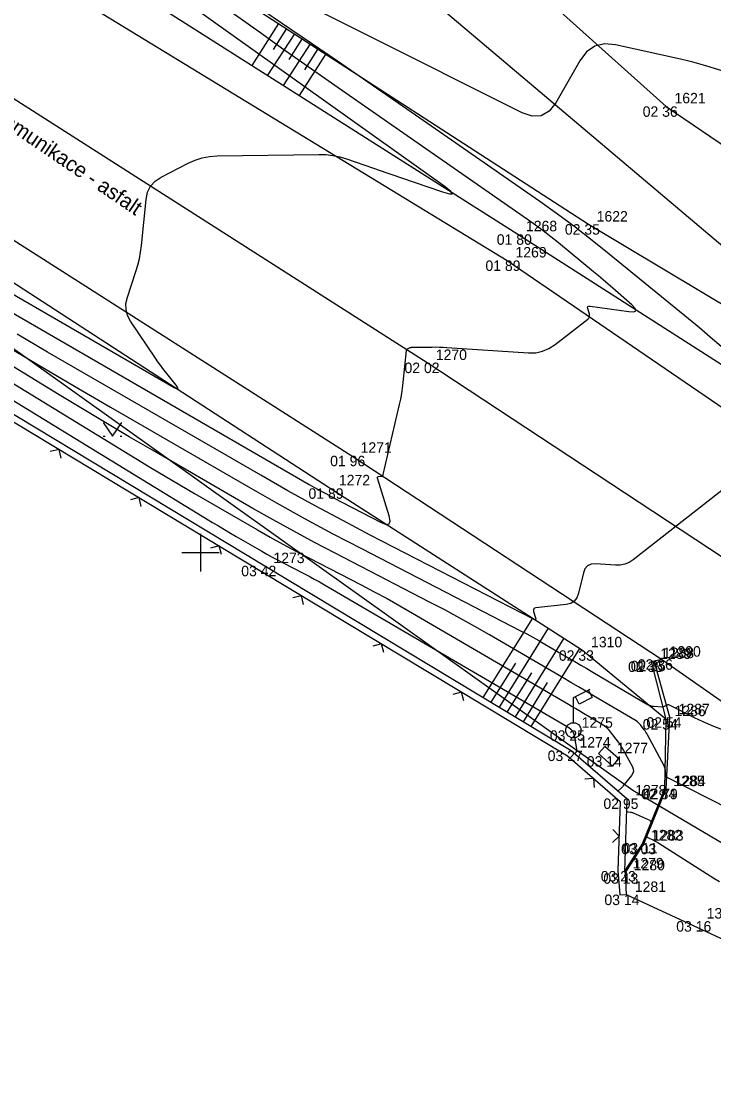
# Model space of a CAD drawing. Extents: x -711234 to -710007, y -1026313 to -1025448.
# Drawn here: x -710604.8 to -710586.27, y -1025538.91 to -1025510.79 of the extents above; entities that cross this region are included whole.
import ezdxf

# ---------------------------------------------------------------- set-up
doc = ezdxf.new("R2010")
doc.units = 0
for name, color, linetype in [('Ex_Major Contours', 7, 'Continuous'), ('Ex_Minor Contours', 7, 'Continuous'), ('Z_body', 7, 'Continuous'), ('Z_body_cisla', 7, 'Continuous'), ('Z_body_vysky_redukovane', 7, 'Continuous'), ('Z_hektometricka_sit', 7, 'Continuous'), ('Z_hrany_paty', 7, 'Continuous'), ('Z_katastr_hranice', 7, 'Continuous'), ('Z_komunikace', 7, 'Continuous'), ('Z_komunikace_osa', 7, 'Continuous'), ('Z_obruba', 7, 'Continuous'), ('Z_pilire', 7, 'Continuous'), ('Z_ploty', 7, 'Continuous'), ('Z_ploty_znacky', 7, 'Continuous'), ('Z_pole_rozhranni', 7, 'Continuous'), ('Z_popisy', 7, 'Continuous'), ('Z_rozhranni', 7, 'Continuous'), ('Z_site_vo_znaky', 7, 'Continuous'), ('Z_technicke_srafy', 7, 'Continuous'), ('Z_vstupy', 7, 'Continuous'), ('Z_znaky_kultur', 7, 'Continuous')]:
    doc.layers.add(name, color=color, linetype=linetype)

# ---------------------------------------------------------------- blocks, each defined once
blk = doc.blocks.new('POINT_DISPLAY')
blk.add_line((0, 0), (0, 0))
blk = doc.blocks.new('Z13')
for p, q in [((0, 0.88), (0.45, 1.1)), ((0, 0.2), (0, 0.88)), ((0.15, 0.7), (0.05, 0.9)), ((0.5, 0.88), (0.15, 0.7)), ((0.4, 1.07), (0.5, 0.88)), ((-0.2, 0.05), (-0.15, 0.15)), ((-0.2, -0.05), (-0.2, 0.05)), ((-0.15, 0.15), (-0.05, 0.2)), ((-0.05, 0.2), (0.05, 0.2)), ((0.05, 0.2), (0.15, 0.15)), ((0.15, 0.15), (0.2, 0.05)), ((0.2, 0.05), (0.2, -0.05)), ((-0.15, -0.15), (-0.2, -0.05)), ((-0.05, -0.2), (-0.15, -0.15)), ((0.05, -0.2), (-0.05, -0.2)), ((0.15, -0.15), (0.05, -0.2)), ((0.2, -0.05), (0.15, -0.15))]:
    blk.add_line(p, q)
blk = doc.blocks.new('Z666')
for p, q in [((-0.25, 0.13), (-0.25, -0.13)), ((0.25, 0.13), (-0.25, 0.13)), ((0.25, -0.13), (0.25, 0.13)), ((-0.25, -0.13), (0.25, -0.13))]:
    blk.add_line(p, q)
blk = doc.blocks.new('Z212')
for p, q in [((-0.17, 0.17), (0, 0)), ((0, 0), (0.17, 0.17))]:
    blk.add_line(p, q)
blk = doc.blocks.new('Z314')
for p, q in [((-0.25, 0.17), (0, -0.2)), ((0, -0.2), (0.25, 0.17)), ((-0.25, -0.2), (-0.2, -0.2)), ((0.2, -0.2), (0.25, -0.2))]:
    blk.add_line(p, q)

msp = doc.modelspace()

# ---------------------------------------------------------------- linework, layer by layer
at = {"layer": 'Ex_Major Contours'}
for points in [[(-710606.138, -1025517.948), (-710597.097, -1025523.174), (-710596.876, -1025523.3), (-710596.653, -1025523.423), (-710596.429, -1025523.544), (-710596.203, -1025523.662), (-710595.169, -1025524.195), (-710595.034, -1025524.247), (-710594.953, -1025524.234), (-710594.927, -1025524.157), (-710594.955, -1025524.015), (-710595.272, -1025523.011), (-710595.275, -1025522.994), (-710595.271, -1025522.981), (-710595.261, -1025522.972), (-710595.244, -1025522.968), (-710595.163, -1025522.959), (-710595.145, -1025522.954), (-710595.131, -1025522.945), (-710595.12, -1025522.932), (-710595.114, -1025522.915), (-710594.677, -1025521.04), (-710594.646, -1025520.894), (-710594.62, -1025520.748), (-710594.598, -1025520.602), (-710594.581, -1025520.454), (-710594.497, -1025519.597), (-710594.494, -1025519.583), (-710594.488, -1025519.571), (-710594.479, -1025519.561), (-710594.467, -1025519.553), (-710594.413, -1025519.525), (-710594.399, -1025519.519), (-710594.385, -1025519.515), (-710594.371, -1025519.512), (-710594.356, -1025519.511), (-710593.805, -1025519.503), (-710593.708, -1025519.502), (-710593.611, -1025519.504), (-710593.514, -1025519.507), (-710593.417, -1025519.513), (-710591.232, -1025519.658), (-710591.039, -1025519.655), (-710590.857, -1025519.617), (-710590.685, -1025519.546), (-710590.523, -1025519.44), (-710589.647, -1025518.755), (-710589.621, -1025518.728), (-710589.605, -1025518.699), (-710589.6, -1025518.665), (-710589.605, -1025518.628), (-710589.647, -1025518.474), (-710589.651, -1025518.441), (-710589.642, -1025518.419), (-710589.622, -1025518.408), (-710589.588, -1025518.408), (-710588.549, -1025518.555), (-710588.418, -1025518.562), (-710588.36, -1025518.535), (-710588.377, -1025518.474), (-710588.467, -1025518.379), (-710588.976, -1025517.931), (-710589.104, -1025517.819), (-710589.233, -1025517.709), (-710589.362, -1025517.6), (-710589.493, -1025517.491), (-710590.432, -1025516.72), (-710590.634, -1025516.558), (-710590.839, -1025516.4), (-710591.047, -1025516.246), (-710591.258, -1025516.096), (-710596.233, -1025512.634), (-710596.768, -1025512.261), (-710597.301, -1025511.887), (-710597.833, -1025511.511), (-710598.364, -1025511.133), (-710601.43, -1025508.946)], [(-710612.856, -1025515.672), (-710601.725, -1025522.486), (-710601.337, -1025522.722), (-710600.947, -1025522.956), (-710600.555, -1025523.187), (-710600.162, -1025523.416), (-710598.479, -1025524.389), (-710598.138, -1025524.583), (-710597.795, -1025524.773), (-710597.45, -1025524.96), (-710597.102, -1025525.142), (-710595.706, -1025525.861), (-710595.359, -1025526.043), (-710595.014, -1025526.23), (-710594.671, -1025526.421), (-710594.331, -1025526.617), (-710590.167, -1025529.05), (-710590.066, -1025529.109), (-710589.965, -1025529.169), (-710589.864, -1025529.228), (-710589.763, -1025529.287), (-710589.309, -1025529.555), (-710589.236, -1025529.603), (-710589.168, -1025529.657), (-710589.106, -1025529.718), (-710589.05, -1025529.786), (-710588.837, -1025530.068), (-710588.785, -1025530.139), (-710588.736, -1025530.213), (-710588.69, -1025530.288), (-710588.647, -1025530.365), (-710588.454, -1025530.726), (-710588.431, -1025530.785), (-710588.427, -1025530.843), (-710588.442, -1025530.898), (-710588.475, -1025530.953), (-710588.707, -1025531.245), (-710588.718, -1025531.258), (-710588.73, -1025531.272), (-710588.742, -1025531.285), (-710588.755, -1025531.297), (-710588.833, -1025531.37)], [(-710588.612, -1025531.916), (-710588.505, -1025531.936), (-710588.487, -1025531.939), (-710588.469, -1025531.944), (-710588.452, -1025531.95), (-710588.435, -1025531.956), (-710588.031, -1025532.13), (-710587.993, -1025532.153), (-710587.97, -1025532.183), (-710587.962, -1025532.22), (-710587.97, -1025532.264), (-710588.058, -1025532.536), (-710588.061, -1025532.548), (-710588.065, -1025532.56), (-710588.072, -1025532.584), (-710588.072, -1025532.59), (-710588.071, -1025532.595), (-710588.068, -1025532.599), (-710588.064, -1025532.602), (-710587.876, -1025532.696), (-710587.843, -1025532.713), (-710587.811, -1025532.731), (-710587.779, -1025532.749), (-710587.747, -1025532.769), (-710586.275, -1025533.7), (-710586.123, -1025533.792)]]:
    msp.add_lwpolyline(points, dxfattribs=at)
at = {"layer": 'Ex_Minor Contours'}
for points in [[(-710601.183, -1025508.56), (-710597.029, -1025511.383), (-710596.333, -1025511.857), (-710595.638, -1025512.334), (-710594.944, -1025512.812), (-710594.251, -1025513.293), (-710590.931, -1025515.603), (-710590.456, -1025515.941), (-710589.988, -1025516.288), (-710589.527, -1025516.643), (-710589.072, -1025517.009), (-710586.958, -1025518.743), (-710586.665, -1025518.986), (-710586.373, -1025519.232), (-710586.084, -1025519.48)], [(-710573.223, -1025517.572), (-710574.002, -1025517.243), (-710574.766, -1025516.876), (-710577.79, -1025515.328), (-710578.551, -1025514.953), (-710579.324, -1025514.603), (-710580.106, -1025514.278), (-710580.9, -1025513.977), (-710585.752, -1025512.226), (-710586.121, -1025512.099), (-710586.494, -1025511.985), (-710586.87, -1025511.883), (-710587.25, -1025511.793), (-710588.909, -1025511.428), (-710589.205, -1025511.402), (-710589.463, -1025511.464), (-710589.682, -1025511.614), (-710589.862, -1025511.85), (-710590.505, -1025512.972), (-710590.682, -1025513.199), (-710590.891, -1025513.32), (-710591.132, -1025513.335), (-710591.405, -1025513.243), (-710599.918, -1025508.97)], [(-710608.19, -1025516.259), (-710600.705, -1025520.585), (-710600.628, -1025520.623), (-710600.594, -1025520.626), (-710600.601, -1025520.591), (-710600.65, -1025520.521), (-710600.933, -1025520.167), (-710601.002, -1025520.078), (-710601.07, -1025519.987), (-710601.136, -1025519.895), (-710601.2, -1025519.802), (-710601.868, -1025518.809), (-710601.949, -1025518.657), (-710601.99, -1025518.5), (-710601.992, -1025518.337), (-710601.954, -1025518.17), (-710601.726, -1025517.488), (-710601.673, -1025517.316), (-710601.631, -1025517.143), (-710601.599, -1025516.967), (-710601.576, -1025516.789), (-710601.455, -1025515.557), (-710601.415, -1025515.367), (-710601.334, -1025515.205), (-710601.213, -1025515.07), (-710601.052, -1025514.963), (-710600.326, -1025514.588), (-710600.141, -1025514.506), (-710599.951, -1025514.446), (-710599.755, -1025514.409), (-710599.554, -1025514.395), (-710596.837, -1025514.356), (-710596.648, -1025514.361), (-710596.462, -1025514.383), (-710596.278, -1025514.421), (-710596.097, -1025514.475), (-710595.377, -1025514.723), (-710595.197, -1025514.785), (-710595.017, -1025514.847), (-710594.836, -1025514.909), (-710594.656, -1025514.971), (-710593.531, -1025515.358), (-710593.341, -1025515.413), (-710593.266, -1025515.409), (-710593.306, -1025515.346), (-710593.462, -1025515.223), (-710601.081, -1025509.788)], [(-710585.859, -1025531.86), (-710587.53, -1025531.006), (-710587.532, -1025531.006), (-710587.534, -1025531.005), (-710587.536, -1025531.006), (-710587.538, -1025531.006), (-710587.546, -1025531.01), (-710587.548, -1025531.011), (-710587.549, -1025531.011), (-710587.55, -1025531.01), (-710587.55, -1025531.008), (-710587.571, -1025530.817), (-710587.576, -1025530.785), (-710587.584, -1025530.754), (-710587.595, -1025530.724), (-710587.609, -1025530.694), (-710588.051, -1025529.868), (-710588.071, -1025529.833), (-710588.092, -1025529.798), (-710588.114, -1025529.765), (-710588.138, -1025529.732), (-710588.235, -1025529.603), (-710588.261, -1025529.572), (-710588.289, -1025529.545), (-710588.32, -1025529.52), (-710588.353, -1025529.498), (-710589.496, -1025528.825), (-710589.698, -1025528.706), (-710589.9, -1025528.587), (-710590.102, -1025528.469), (-710590.304, -1025528.35), (-710592.271, -1025527.201), (-710592.668, -1025526.973), (-710593.067, -1025526.75), (-710593.47, -1025526.532), (-710593.875, -1025526.32), (-710596.401, -1025525.017), (-710596.955, -1025524.727), (-710597.506, -1025524.43), (-710598.054, -1025524.127), (-710598.598, -1025523.817), (-710601.282, -1025522.265), (-710601.909, -1025521.9), (-710602.534, -1025521.531), (-710603.156, -1025521.158), (-710603.776, -1025520.782), (-710612.619, -1025515.368)], [(-710613.093, -1025515.976), (-710599.675, -1025524.191), (-710599.517, -1025524.286), (-710599.359, -1025524.381), (-710599.201, -1025524.475), (-710599.042, -1025524.567), (-710598.361, -1025524.961), (-710598.223, -1025525.04), (-710598.084, -1025525.117), (-710597.944, -1025525.192), (-710597.803, -1025525.266), (-710597.238, -1025525.557), (-710597.098, -1025525.631), (-710596.958, -1025525.706), (-710596.819, -1025525.784), (-710596.682, -1025525.863), (-710590.153, -1025529.678), (-710590.098, -1025529.718), (-710590.055, -1025529.767), (-710590.025, -1025529.825), (-710590.007, -1025529.891), (-710589.94, -1025530.293), (-710589.939, -1025530.302), (-710589.941, -1025530.312), (-710589.945, -1025530.32), (-710589.951, -1025530.327), (-710589.997, -1025530.37)], [(-710584.755, -1025522.311), (-710588.435, -1025525.191), (-710588.543, -1025525.262), (-710588.658, -1025525.31), (-710588.78, -1025525.335), (-710588.91, -1025525.337), (-710589.44, -1025525.302), (-710589.56, -1025525.311), (-710589.654, -1025525.354), (-710589.723, -1025525.431), (-710589.766, -1025525.543), (-710589.892, -1025526.087), (-710589.936, -1025526.206), (-710590.007, -1025526.295), (-710590.104, -1025526.355), (-710590.227, -1025526.385), (-710591.034, -1025526.476), (-710591.071, -1025526.485), (-710591.093, -1025526.504), (-710591.101, -1025526.532), (-710591.095, -1025526.57), (-710591.042, -1025526.738), (-710591.035, -1025526.773), (-710591.042, -1025526.792), (-710591.061, -1025526.795), (-710591.094, -1025526.782), (-710595.46, -1025524.531), (-710596.199, -1025524.145), (-710596.932, -1025523.749), (-710597.661, -1025523.346), (-710598.385, -1025522.933), (-710604.085, -1025519.638), (-710604.899, -1025519.164)], [(-710604.976, -1025519.594), (-710604.121, -1025520.106), (-710603.264, -1025520.613), (-710602.403, -1025521.114), (-710598.717, -1025523.245), (-710597.97, -1025523.671), (-710597.218, -1025524.087), (-710596.461, -1025524.495), (-710595.699, -1025524.893), (-710591.443, -1025527.088), (-710591.279, -1025527.174), (-710591.116, -1025527.262), (-710590.955, -1025527.352), (-710590.794, -1025527.445), (-710590.154, -1025527.818), (-710589.994, -1025527.912), (-710589.835, -1025528.006), (-710589.675, -1025528.1), (-710589.515, -1025528.193), (-710588.051, -1025529.056), (-710588.013, -1025529.075), (-710587.974, -1025529.09), (-710587.933, -1025529.1), (-710587.891, -1025529.106), (-710587.654, -1025529.124), (-710587.643, -1025529.124), (-710587.633, -1025529.123), (-710587.622, -1025529.12), (-710587.612, -1025529.116), (-710587.557, -1025529.088), (-710587.551, -1025529.086), (-710587.54, -1025529.083), (-710587.535, -1025529.08), (-710587.51, -1025529.062), (-710587.506, -1025529.06), (-710587.501, -1025529.058), (-710587.496, -1025529.059), (-710587.491, -1025529.061), (-710586.804, -1025529.406), (-710586.687, -1025529.463), (-710586.569, -1025529.517), (-710586.45, -1025529.568), (-710586.329, -1025529.617), (-710584.508, -1025530.326)]]:
    msp.add_lwpolyline(points, dxfattribs=at)
at = {"layer": 'Z_hektometricka_sit'}
for p, q in [((-710600, -1025524.5), (-710600, -1025525.5)), ((-710600.5, -1025525), (-710599.5, -1025525))]:
    msp.add_line(p, q, dxfattribs=at)
at = {"layer": 'Z_hrany_paty'}
for p, q in [((-710601.64, -1025508.44), (-710589.63, -1025516.22)), ((-710601.22, -1025510.33), (-710591.52, -1025516.49)), ((-710611.31, -1025513.69), (-710596.53, -1025523.28)), ((-710589.63, -1025516.22), (-710581.54, -1025521.06)), ((-710591.52, -1025516.49), (-710579.78, -1025523.99)), ((-710596.53, -1025523.28), (-710589.79, -1025527.61)), ((-710589.79, -1025527.61), (-710587.55, -1025529.45))]:
    msp.add_line(p, q, dxfattribs=at)
at = {"layer": 'Z_katastr_hranice'}
for points in [[(-710600.21, -1025504.82), (-710580.45, -1025521.54), (-710492.86, -1025583.88), (-710429.93, -1025627.5), (-710391.58, -1025654.85), (-710379.57, -1025662.83), (-710367.07, -1025673.36), (-710347.9, -1025691.71), (-710333.8, -1025705.97), (-710271.15, -1025774.38), (-710237.36, -1025811.14)], [(-710577.81, -1025537.82), (-710583.33, -1025534.38), (-710588.44, -1025531.36), (-710611.74, -1025514.75), (-710620.52, -1025511.94)]]:
    msp.add_lwpolyline(points, dxfattribs=at)
at = {"layer": 'Z_komunikace'}
for p, q in [((-710607.1, -1025507.86), (-710591.8, -1025517.19)), ((-710610.81, -1025512.94), (-710595.95, -1025522.41)), ((-710591.8, -1025517.19), (-710579.11, -1025525.87)), ((-710595.95, -1025522.41), (-710587.68, -1025527.85)), ((-710587.68, -1025527.85), (-710580.62, -1025532.78))]:
    msp.add_line(p, q, dxfattribs=at)
at = {"layer": 'Z_komunikace_osa'}
for p, q in [((-710608.89, -1025510.38), (-710593.94, -1025519.92)), ((-710593.94, -1025519.92), (-710579.13, -1025529.68))]:
    msp.add_line(p, q, dxfattribs=at)
at = {"layer": 'Z_obruba'}
for p, q in [((-710587.94, -1025527.91), (-710587.87, -1025527.89)), ((-710587.55, -1025529.45), (-710587.94, -1025527.91)), ((-710587.59, -1025531.31), (-710587.55, -1025529.45)), ((-710588.18, -1025532.76), (-710587.59, -1025531.31)), ((-710588.18, -1025532.76), (-710588.67, -1025533.51))]:
    msp.add_line(p, q, dxfattribs=at)
at = {"layer": 'Z_ploty'}
for p, q in [((-710613.42, -1025516.43), (-710598.37, -1025525.5)), ((-710613.33, -1025516.28), (-710598.28, -1025525.35)), ((-710598.37, -1025525.5), (-710590.19, -1025530.43)), ((-710598.28, -1025525.35), (-710590.09, -1025530.29)), ((-710590.09, -1025530.29), (-710588.6, -1025531.57)), ((-710590.19, -1025530.43), (-710588.78, -1025531.65)), ((-710588.78, -1025531.65), (-710588.84, -1025533.5)), ((-710588.6, -1025531.57), (-710588.67, -1025533.51)), ((-710588.84, -1025533.5), (-710588.79, -1025534.15)), ((-710588.67, -1025533.51), (-710588.65, -1025533.57)), ((-710588.65, -1025533.57), (-710588.62, -1025534.14)), ((-710588.79, -1025534.15), (-710588.62, -1025534.14))]:
    msp.add_line(p, q, dxfattribs=at)
at = {"layer": 'Z_pole_rozhranni'}
for p, q in [((-710593.34, -1025507.89), (-710587.55, -1025513.07)), ((-710587.55, -1025513.07), (-710579.54, -1025518.54))]:
    msp.add_line(p, q, dxfattribs=at)
at = {"layer": 'Z_rozhranni'}
for p, q in [((-710587.87, -1025527.89), (-710587.68, -1025527.85)), ((-710587.45, -1025529.4), (-710587.87, -1025527.89)), ((-710587.55, -1025531.31), (-710587.45, -1025529.4)), ((-710588.15, -1025532.78), (-710587.55, -1025531.31)), ((-710588.65, -1025533.57), (-710588.15, -1025532.78))]:
    msp.add_line(p, q, dxfattribs=at)
at = {"layer": 'Z_technicke_srafy'}
for p, q in [((-710597.91, -1025510.86), (-710598.63, -1025511.98)), ((-710597.49, -1025511.13), (-710598.21, -1025512.24)), ((-710597.7, -1025510.99), (-710598.06, -1025511.55)), ((-710597.07, -1025511.4), (-710597.79, -1025512.51)), ((-710597.28, -1025511.26), (-710597.64, -1025511.82)), ((-710596.65, -1025511.67), (-710597.36, -1025512.78)), ((-710596.86, -1025511.53), (-710597.22, -1025512.09)), ((-710592.44, -1025528.87), (-710591.12, -1025526.75)), ((-710592.01, -1025529.13), (-710590.7, -1025527.02)), ((-710591.58, -1025529.39), (-710590.28, -1025527.29)), ((-710591.16, -1025529.65), (-710589.86, -1025527.56)), ((-710592.23, -1025529), (-710591.57, -1025527.95)), ((-710591.8, -1025529.26), (-710591.14, -1025528.21)), ((-710591.37, -1025529.52), (-710590.72, -1025528.47))]:
    msp.add_line(p, q, dxfattribs=at)
at = {"layer": 'Z_vstupy'}
msp.add_line((-710588.62, -1025534.14), (-710585.06, -1025535.79), dxfattribs=at)

# ---------------------------------------------------------------- block references
at = {"layer": 'Z_body'}
for p in [(-710587.55, -1025513.07), (-710589.63, -1025516.22), (-710591.52, -1025516.49), (-710591.8, -1025517.19), (-710593.94, -1025519.92), (-710595.95, -1025522.41), (-710596.53, -1025523.28), (-710598.28, -1025525.35), (-710589.79, -1025527.61), (-710587.94, -1025527.91), (-710587.87, -1025527.89), (-710587.68, -1025527.85), (-710587.55, -1025529.45), (-710587.45, -1025529.4), (-710590.03, -1025529.75), (-710590.09, -1025530.29), (-710589.09, -1025530.44), (-710587.59, -1025531.31), (-710587.55, -1025531.31), (-710588.6, -1025531.57), (-710588.18, -1025532.76), (-710588.15, -1025532.78), (-710588.67, -1025533.51), (-710588.65, -1025533.57), (-710588.62, -1025534.14), (-710586.7, -1025534.85)]:
    msp.add_blockref('POINT_DISPLAY', p, dxfattribs=at)
at = {"layer": 'Z_pilire', "rotation": -41.399999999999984}
msp.add_blockref('Z666', (-710589.09, -1025530.44), dxfattribs=at)
at = {"layer": 'Z_ploty_znacky'}
for p, rotation in [((-710603.78, -1025522.24), 148.9), ((-710601.64, -1025523.53), 148.9), ((-710599.5, -1025524.82), 148.9), ((-710597.3, -1025526.15), 148.9), ((-710595.16, -1025527.44), 148.9), ((-710593.02, -1025528.73), 148.9), ((-710589.49, -1025531.04), 139.3), ((-710588.81, -1025532.58), 87.9)]:
    msp.add_blockref('Z212', p, dxfattribs=dict(at, rotation=rotation))
at = {"layer": 'Z_site_vo_znaky'}
msp.add_blockref('Z13', (-710590.03, -1025529.75), dxfattribs=at)
at = {"layer": 'Z_znaky_kultur'}
msp.add_blockref('Z314', (-710602.35, -1025521.69), dxfattribs=at)

# ---------------------------------------------------------------- texts
at = {"layer": 'Z_body_cisla'}
for s, p in [('1621', (-710587.33, -1025512.99)), ('1622', (-710589.41, -1025516.15)), ('1268', (-710591.3, -1025516.41)), ('1269', (-710591.58, -1025517.11)), ('1270', (-710593.71, -1025519.85)), ('1271', (-710595.72, -1025522.33)), ('1272', (-710596.3, -1025523.2)), ('1273', (-710598.05, -1025525.28)), ('1310', (-710589.56, -1025527.53)), ('1290', (-710587.46, -1025527.78)), ('1289', (-710587.71, -1025527.84)), ('1288', (-710587.64, -1025527.82)), ('1286', (-710587.33, -1025529.37)), ('1287', (-710587.22, -1025529.32)), ('1275', (-710589.81, -1025529.68)), ('1274', (-710589.87, -1025530.21)), ('1277', (-710588.87, -1025530.36)), ('1285', (-710587.36, -1025531.24)), ('1284', (-710587.33, -1025531.24)), ('1278', (-710588.38, -1025531.49)), ('1282', (-710587.96, -1025532.69)), ('1283', (-710587.92, -1025532.7)), ('1279', (-710588.45, -1025533.44)), ('1280', (-710588.42, -1025533.49)), ('1281', (-710588.39, -1025534.07)), ('1303', (-710586.47, -1025534.78))]:
    msp.add_text(s, height=0.28, dxfattribs=at).set_placement(p)
at = {"layer": 'Z_body_vysky_redukovane'}
for s, p in [('02 36', (-710588.18, -1025513.35)), ('02 35', (-710590.26, -1025516.5)), ('01 80', (-710592.08, -1025516.77)), ('01 89', (-710592.383, -1025517.47)), ('02 02', (-710594.547, -1025520.2)), ('01 96', (-710596.533, -1025522.69)), ('01 89', (-710597.113, -1025523.56)), ('03 42', (-710598.91, -1025525.63)), ('02 33', (-710590.42, -1025527.89)), ('02 35', (-710588.57, -1025528.19)), ('02 35', (-710588.5, -1025528.17)), ('02 36', (-710588.31, -1025528.13)), ('02 54', (-710588.18, -1025529.73)), ('02 54', (-710588.08, -1025529.68)), ('03 25', (-710590.66, -1025530.03)), ('03 27', (-710590.72, -1025530.57)), ('03 14', (-710589.673, -1025530.72)), ('02 84', (-710588.22, -1025531.59)), ('02 79', (-710588.18, -1025531.59)), ('02 95', (-710589.23, -1025531.85)), ('03 03', (-710588.757, -1025533.06)), ('03 11', (-710588.717, -1025533.04)), ('03 23', (-710589.3, -1025533.79)), ('03 13', (-710589.233, -1025533.85)), ('03 14', (-710589.203, -1025534.42)), ('03 16', (-710587.283, -1025535.13))]:
    msp.add_text(s, height=0.28, dxfattribs=at).set_placement(p)
at = {"layer": 'Z_popisy'}
msp.add_text('Komunikace - asfalt', height=0.4, rotation=325.8, dxfattribs=at).set_placement((-710605.62, -1025513.36))

doc.saveas('drawing.dxf')
